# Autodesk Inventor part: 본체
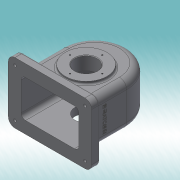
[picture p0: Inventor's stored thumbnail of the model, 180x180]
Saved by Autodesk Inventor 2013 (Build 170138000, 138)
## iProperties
Created: 2016-10
Part Number: 본체
Material: 일반
Document SubType Name: Modeling
Designer: dgall
Density: 1 g/cm^3
Author: dgall
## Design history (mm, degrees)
sketch "스케치1"
  geometry: L1 (-58, 0)-(-58, -80); L2 (58, 0)-(58, -80); L3 (58, -80)-(-58, -80); A1 r 58 centre (0, 0) between (58, 0) and (-58, 0); 1 further point
  constraints: 6 end point, 2 point on circle, 2 tangent, 1 centre point, 1 coincident, 1 parallel, 1 perpendicular, 1 vertical
  dimensions: "d0" = 116 diameter of A1; "d2" = 80 distance of L1.start L1.end
extrude "돌출1" new body sketch "스케치1" distance "d3" = 77; taper "d4" = 0 deg
node "작업 평면2"
sketch "스케치3"
  geometry: L1 (58, 0)-(58, -80) reference; L2 (58, -80)-(-58, -80) reference; L3 (-58, -80)-(-58, 0) reference; L4 (-52, 0)-(-52, -80); L5 (52, 0)-(52, -80); A1 r 52 centre (0, 0) between (52, 0) and (-52, 0); A2 r 58 centre (0, 0) between (58, 0) and (-58, 0) reference; 1 further point
  constraints: 4 end point, 2 perpendicular, 2 point on circle, 2 point on line, 2 tangent, 1 centre point, 1 coincident
  dimensions: "d11" = 104 diameter of A1
extrude "돌출3" cut sketch "스케치3" distance "d13" = 67; taper "d14" = 0 deg
sketch "스케치4"
  geometry: L1 (-58, -80)-(58, -80) reference; C1 r 37.5 at (0, -15); A1 r 58 centre (0, 0) between (58, 0) and (-58, 0) reference
  constraints: 1 centre point, 1 vertical alignment
  dimensions: "d15" = 75 diameter of C1; "d17" = 65 distance from line of C1.centre L1
extrude "돌출4" join sketch "스케치4" distance "d18" = 5; taper "d19" = 0 deg
sketch "스케치5"
  geometry: L1 (-58, -80)-(58, -80) reference; C1 r 31 at (0, -15); A1 r 58 centre (0, 0) between (58, 0) and (-58, 0) reference
  constraints: 1 centre point, 1 vertical alignment
  dimensions: "d20" = 62 diameter of C1; "d22" = 65 distance from line of L1 C1.centre
extrude "돌출5" join sketch "스케치5" distance "d23" = 10; taper "d24" = 0 deg
sketch "스케치6"
  geometry: C1 r 31 at (0, 0) reference; C2 r 20 at (0, 0); 1 further point
  constraints: 1 centre point, 1 coincident
  dimensions: "d25" = 40 diameter of C2
extrude "돌출6" cut sketch "스케치6" stored distance "d27" = 10; taper "d28" = 0 deg
sketch "스케치7"
  geometry: L1 (-35, 82)-(5, 82) reference; L2 (5, -10)-(-35, -10) reference; L3 (-15, 82)-(-15, -10); L4 (5, 58)-(13, 58); L5 (52, 72)-(0, 72) reference; L6 (13, 58)-(24.747, 72); L7 (5, 72)-(5, 82) reference; L8 (5, 58)-(5, 72); L9 (24.747, 72)-(5, 72); 1 further point
  constraints: 10 end point, 2 collinear, 2 midpoint, 1 perpendicular, 1 point on line, 1 vertical alignment
  dimensions: "d29" = 24 distance of L4.start L1.end; "d30" = 50 deg angle of L4 L6; "d31" = 56 diameter of L4.end L3
revolve "회전1" sketch "스케치7" stored, may be unused: angle "d32" = 90 deg
sketch "스케치8"
  geometry: C1 r 20 at (0, 0) reference; 2 further points
  constraints: 1 vertical alignment
  dimensions: "d33" = 29 distance of C1.centre point (0, 29)
hole "구멍1" sketch "스케치8" at (0, 29) diameter "d34" = 2.459; stored, may be unused: countersink angle "d38" = 90 deg, drill point angle "d40" = 118 deg; dims "d35" = 6, "d36" = 4, "d37" = 2, "d39" = 8
sketch "스케치9"
  geometry: C1 r 20 at (0, 0) reference; 2 further points
  constraints: 1 vertical alignment
  dimensions: "d44" = 26 distance of C1.centre point (0, 26)
hole "구멍2" sketch "스케치9" at (0, 26) diameter "d45" = 2.459; stored, may be unused: countersink angle "d49" = 90 deg, drill point angle "d51" = 118 deg; dims "d46" = 6, "d47" = 4, "d48" = 2, "d50" = 8
sketch "스케치10"
  geometry: L1 (116, 0)-(0, 0) reference; L2 (116, 0)-(116, 77) reference; L3 (0, 77)-(116, 77) reference; L4 (0, 0)-(0, 77) reference; L5 (-17, 93.5)-(133, 93.5); L6 (133, 93.5)-(133, -16.5); L7 (133, -16.5)-(-17, -16.5); L8 (-17, -16.5)-(-17, 93.5); 5 further points
  constraints: 8 end point, 4 midpoint, 2 parallel, 1 horizontal, 1 horizontal alignment, 1 perpendicular, 1 vertical alignment
  dimensions: "d55" = 150 distance of L5.start L5.end; "d57" = 110 distance of L7.end L5.start
extrude "돌출7" join sketch "스케치10" distance "d58" = 15; taper "d59" = 0 deg
node "작업 평면3"
sketch "스케치11"
  geometry: L1 (-150, 0)-(-150, -110) reference; L2 (-150, -110)-(0, -110) reference; L3 (0, 0)-(-150, 0) reference; L4 (0, -110)-(0, 0) reference; C1 r 6 at (-75, -55); 1 further point
  constraints: 1 centre point
  dimensions: "d61" = 12 diameter of C1; "d63" = 55 distance from line of C1.centre L2; "d64" = 75 distance from line of L1 C1.centre
extrude "돌출8" join sketch "스케치11" stored distance "d65" = 15; taper "d66" = 0 deg
sketch "스케치12"
  geometry: L1 (64, 44.5)-(64, 32.5) reference; L2 (64, 44.5)-(58, 44.5) reference; L3 (64, 44.5)-(52, 46.616); L4 (58, 0)-(58, 77) reference; L5 (52, 5)-(52, 72) reference; L6 (52, 46.616)-(52, 38.5); L7 (64, 44.5)-(64, 38.5); L8 (64, 38.5)-(52, 38.5); 1 further point
  constraints: 8 end point, 2 midpoint, 1 collinear, 1 perpendicular, 1 point on line
  dimensions: "d68" = 100 deg angle of L4 L3
revolve "회전2" sketch "스케치12" stored, may be unused: angle "d69" = 90 deg
sketch "스케치13"
  geometry: C1 r 6 at (0, 0) reference; 1 further point
hole "구멍3" sketch "스케치13" at (0, 0) diameter "d70" = 4.459; stored, may be unused: countersink angle "d74" = 90 deg, drill point angle "d76" = 118 deg; dims "d71" = 6, "d72" = 4, "d73" = 2, "d75" = 8
chamfer "모따기1" distance "d77" = 1; stored, may be unused: second distance "d78" = 2, angle "d79" = 45 deg
fillet "모깎기1" dims "d80" = 13
fillet "모깎기2" dims "d81" = 12
sketch "스케치14"
  geometry: A1 r 12 centre (-5, -81.5) between (-17, -81.5) and (-5, -93.5) reference; A2 r 12 centre (121, -81.5) between (121, -93.5) and (133, -81.5) reference; A3 r 12 centre (121, 4.5) between (133, 4.5) and (121, 16.5) reference; A4 r 12 centre (-5, 4.5) between (-5, 16.5) and (-17, 4.5) reference; 1 further point
hole "구멍4" sketch "스케치14" at (-5, -81.5), (121, -81.5), (-5, 4.5), (121, 4.5) diameter "d82" = 5; stored, may be unused: countersink angle "d86" = 90 deg, drill point angle "d88" = 118 deg; dims "d83" = 6, "d84" = 12, "d85" = 5, "d87" = 8
fillet "모깎기3" dims "d89" = 8
fillet "모깎기4" dims "d90" = 3
fillet "모깎기5" dims "d91" = 3
fillet "모깎기6" dims "d92" = 3
sketch "스케치15"
  geometry: L1 (-17.5, -80)-(68.5, -80) reference; L2 (-13, 0)-(-13, -62) reference; 2 further points
  constraints: 1 other
  dimensions: "d93" = 40 distance from line of L1 point (25.5, -40); "d94" = 38.5 distance from line of L2 point (25.5, -40)
feature "엠보싱1" sketch "스케치15" dims "d0" = 116, "d2" = 80, "d95" = 0.5, "d96" = 0
node "솔리드1"
pattern_circular "원형 패턴1" dims angle "d42" = 360 deg
pattern_circular "원형 패턴2" dims angle "d53" = 360 deg
node "절단 모서리 투영2"
other parameters: "d10" = 5, "d60" = -144
